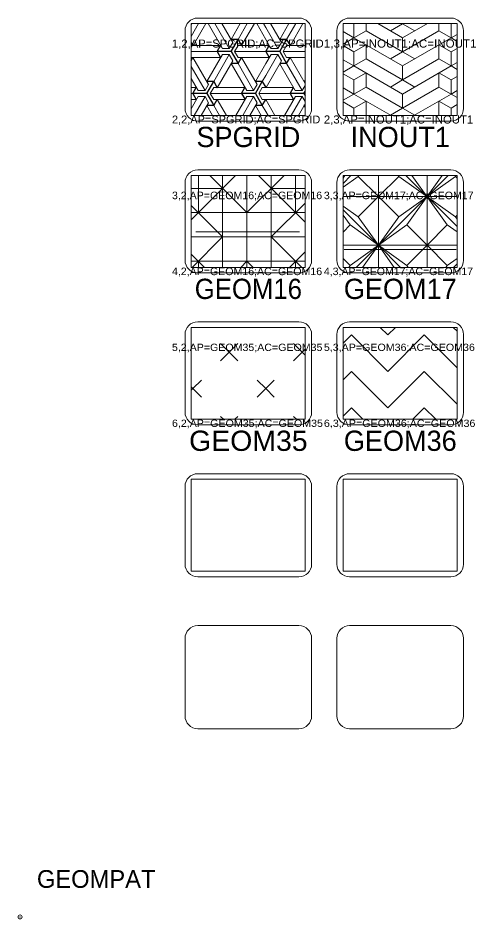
# Model space of a CAD drawing. Extents: x 95935 to 95946.4, y 95971.2 to 95974.7.
# Drawn here: x 95935.026 to 95936.835, y 95971.173 to 95974.732 of the extents above; entities that cross this region are included whole.
import ezdxf
from ezdxf.enums import TextEntityAlignment as Align

# ---------------------------------------------------------------- set-up
doc = ezdxf.new("R2010")
doc.units = 0
doc.header["$LTSCALE"] = 0.032
doc.header["$PDMODE"] = 32
doc.header["$PDSIZE"] = 0.016
for name, color, linetype, lineweight in [('1', 7, 'Continuous', 13), ('2', 7, 'Continuous', 13), ('25', 7, 'Continuous', 13), ('6', 7, 'Continuous', 13), ('63', 7, 'Continuous', 13)]:
    doc.layers.add(name, color=color, linetype=linetype, lineweight=lineweight)
doc.layers.add('20', color=7, linetype='Continuous')
doc.layers.add('8', color=7, linetype='Continuous')

msp = doc.modelspace()

# ---------------------------------------------------------------- linework, layer by layer
at = {"layer": '1'}
for p, q in [((95935.7357, 95974.7318), (95936.1357, 95974.7318)), ((95936.3357, 95974.7318), (95936.7357, 95974.7318)), ((95935.6857, 95974.3747), (95935.6857, 95974.6818)), ((95936.1857, 95974.6818), (95936.1857, 95974.3747)), ((95936.2857, 95974.3747), (95936.2857, 95974.6818)), ((95936.7857, 95974.6818), (95936.7857, 95974.3747)), ((95936.1357, 95974.3247), (95935.7357, 95974.3247)), ((95936.7357, 95974.3247), (95936.3357, 95974.3247)), ((95935.7357, 95974.1318), (95936.1357, 95974.1318)), ((95936.3357, 95974.1318), (95936.7357, 95974.1318)), ((95935.6857, 95973.7747), (95935.6857, 95974.0818)), ((95936.1857, 95974.0818), (95936.1857, 95973.7747)), ((95936.2857, 95973.7747), (95936.2857, 95974.0818)), ((95936.7857, 95974.0818), (95936.7857, 95973.7747)), ((95936.1357, 95973.7247), (95935.7357, 95973.7247)), ((95936.7357, 95973.7247), (95936.3357, 95973.7247)), ((95935.7357, 95973.5318), (95936.1357, 95973.5318)), ((95936.3357, 95973.5318), (95936.7357, 95973.5318)), ((95935.6857, 95973.1747), (95935.6857, 95973.4818)), ((95936.1857, 95973.4818), (95936.1857, 95973.1747)), ((95936.2857, 95973.1747), (95936.2857, 95973.4818)), ((95936.7857, 95973.4818), (95936.7857, 95973.1747)), ((95936.1357, 95973.1247), (95935.7357, 95973.1247)), ((95936.7357, 95973.1247), (95936.3357, 95973.1247)), ((95935.7357, 95972.9318), (95936.1357, 95972.9318)), ((95936.3357, 95972.9318), (95936.7357, 95972.9318)), ((95935.6857, 95972.5747), (95935.6857, 95972.8818)), ((95936.1857, 95972.8818), (95936.1857, 95972.5747)), ((95936.2857, 95972.5747), (95936.2857, 95972.8818)), ((95936.7857, 95972.8818), (95936.7857, 95972.5747)), ((95936.1357, 95972.5247), (95935.7357, 95972.5247)), ((95936.7357, 95972.5247), (95936.3357, 95972.5247)), ((95935.7357, 95972.3318), (95936.1357, 95972.3318)), ((95936.3357, 95972.3318), (95936.7357, 95972.3318)), ((95935.6857, 95971.9747), (95935.6857, 95972.2818)), ((95936.1857, 95972.2818), (95936.1857, 95971.9747)), ((95936.2857, 95971.9747), (95936.2857, 95972.2818)), ((95936.7857, 95972.2818), (95936.7857, 95971.9747)), ((95936.1357, 95971.9247), (95935.7357, 95971.9247)), ((95936.7357, 95971.9247), (95936.3357, 95971.9247))]:
    msp.add_line(p, q, dxfattribs=at)
for centre, start, end in [((95935.7357, 95974.6818), 90, 180), ((95936.1357, 95974.6818), 0, 90), ((95936.3357, 95974.6818), 90, 180), ((95936.7357, 95974.6818), 0, 90), ((95935.7357, 95974.3747), 180, 270), ((95936.1357, 95974.3747), 270, 0), ((95936.3357, 95974.3747), 180, 270), ((95936.7357, 95974.3747), 270, 0), ((95935.7357, 95974.0818), 90, 180), ((95936.1357, 95974.0818), 0, 90), ((95936.3357, 95974.0818), 90, 180), ((95936.7357, 95974.0818), 0, 90), ((95935.7357, 95973.7747), 180, 270), ((95936.1357, 95973.7747), 270, 0), ((95936.3357, 95973.7747), 180, 270), ((95936.7357, 95973.7747), 270, 0), ((95935.7357, 95973.4818), 90, 180), ((95936.1357, 95973.4818), 0, 90), ((95936.3357, 95973.4818), 90, 180), ((95936.7357, 95973.4818), 0, 90), ((95935.7357, 95973.1747), 180, 270), ((95936.1357, 95973.1747), 270, 0), ((95936.3357, 95973.1747), 180, 270), ((95936.7357, 95973.1747), 270, 0), ((95935.7357, 95972.8818), 90, 180), ((95936.1357, 95972.8818), 0, 90), ((95936.3357, 95972.8818), 90, 180), ((95936.7357, 95972.8818), 0, 90), ((95935.7357, 95972.5747), 180, 270), ((95936.1357, 95972.5747), 270, 0), ((95936.3357, 95972.5747), 180, 270), ((95936.7357, 95972.5747), 270, 0), ((95935.7357, 95972.2818), 90, 180), ((95936.1357, 95972.2818), 0, 90), ((95936.3357, 95972.2818), 90, 180), ((95936.7357, 95972.2818), 0, 90), ((95935.7357, 95971.9747), 180, 270), ((95936.1357, 95971.9747), 270, 0), ((95936.3357, 95971.9747), 180, 270), ((95936.7357, 95971.9747), 270, 0)]:
    msp.add_arc(centre, 0.05, start, end, dxfattribs=at)
at = {"layer": '2'}
for points in [[(95936.1601, 95974.7099), (95935.7097, 95974.7099), (95935.7097, 95974.3468), (95936.1601, 95974.3468)], [(95936.7601, 95974.7099), (95936.3097, 95974.7099), (95936.3097, 95974.3468), (95936.7601, 95974.3468)], [(95936.1601, 95974.1099), (95935.7097, 95974.1099), (95935.7097, 95973.7468), (95936.1601, 95973.7468)], [(95936.7601, 95974.1099), (95936.3097, 95974.1099), (95936.3097, 95973.7468), (95936.7601, 95973.7468)], [(95936.1601, 95973.5099), (95935.7097, 95973.5099), (95935.7097, 95973.1468), (95936.1601, 95973.1468)], [(95936.7601, 95973.5099), (95936.3097, 95973.5099), (95936.3097, 95973.1468), (95936.7601, 95973.1468)], [(95936.1601, 95972.9099), (95935.7097, 95972.9099), (95935.7097, 95972.5468), (95936.1601, 95972.5468)], [(95936.7601, 95972.9099), (95936.3097, 95972.9099), (95936.3097, 95972.5468), (95936.7601, 95972.5468)]]:
    msp.add_lwpolyline(points, close=True, dxfattribs=at)
at = {"layer": '25'}
msp.add_line((95935.7278, 95973.8875), (95936.1378, 95973.8875), dxfattribs=at)
at = {"layer": '6'}
for p, q in [((95935.7097, 95974.7059), (95935.712, 95974.7099)), ((95935.7097, 95974.6592), (95935.739, 95974.7099)), ((95935.7177, 95974.6236), (95935.7675, 95974.7099)), ((95935.7765, 95974.7099), (95935.8332, 95974.6118)), ((95935.8039, 95974.7099), (95935.8606, 95974.6118)), ((95935.8314, 95974.7099), (95935.8743, 95974.6355)), ((95935.8679, 95974.6474), (95935.904, 95974.7099)), ((95935.8949, 95974.6474), (95935.931, 95974.7099)), ((95935.9092, 95974.6227), (95935.9595, 95974.7099)), ((95935.9686, 95974.7099), (95936.0046, 95974.6474)), ((95935.996, 95974.7099), (95936.0046, 95974.6949)), ((95936.0046, 95974.6949), (95936.0526, 95974.6118)), ((95936.0234, 95974.7099), (95936.0663, 95974.6355)), ((95936.0597, 95974.647), (95936.096, 95974.7099)), ((95936.0869, 95974.6474), (95936.123, 95974.7099)), ((95936.1017, 95974.6236), (95936.1515, 95974.7099)), ((95936.3526, 95974.7087), (95936.3505, 95974.7099)), ((95936.3526, 95974.7087), (95936.3547, 95974.7099)), ((95936.3526, 95974.6533), (95936.3526, 95974.7087)), ((95936.4006, 95974.681), (95936.4006, 95974.7099)), ((95936.5446, 95974.6533), (95936.4465, 95974.7099)), ((95936.5446, 95974.7087), (95936.4966, 95974.681)), ((95936.5425, 95974.7099), (95936.5446, 95974.7087)), ((95936.5446, 95974.6533), (95936.6427, 95974.7099)), ((95936.5446, 95974.7099), (95936.5446, 95974.7087)), ((95936.5467, 95974.7099), (95936.5446, 95974.7087)), ((95936.5446, 95974.7087), (95936.5926, 95974.681)), ((95936.6886, 95974.681), (95936.6886, 95974.7099)), ((95936.7366, 95974.7087), (95936.7345, 95974.7099)), ((95936.7366, 95974.7087), (95936.7387, 95974.7099)), ((95936.7366, 95974.6533), (95936.7366, 95974.7087)), ((95936.3526, 95974.6533), (95936.3097, 95974.6781)), ((95936.3526, 95974.6533), (95936.3097, 95974.6285)), ((95936.3526, 95974.6533), (95936.4006, 95974.681)), ((95936.3526, 95974.6533), (95936.4486, 95974.5979)), ((95936.4006, 95974.681), (95936.5446, 95974.5979)), ((95936.6886, 95974.681), (95936.5446, 95974.5979)), ((95936.5446, 95974.6533), (95936.5446, 95974.5979)), ((95936.7366, 95974.6533), (95936.6406, 95974.5979)), ((95936.7366, 95974.6533), (95936.6886, 95974.681)), ((95936.7366, 95974.6533), (95936.7601, 95974.6669)), ((95936.7366, 95974.6533), (95936.7601, 95974.6397)), ((95935.7097, 95974.6236), (95935.8263, 95974.6236)), ((95935.8606, 95974.6118), (95935.8743, 95974.6355)), ((95935.8812, 95974.5999), (95935.8949, 95974.6236)), ((95935.8949, 95974.6236), (95936.0046, 95974.6236)), ((95936.0046, 95974.6474), (95936.0252, 95974.6118)), ((95936.0046, 95974.6236), (95936.0183, 95974.6236)), ((95936.0526, 95974.6118), (95936.0663, 95974.6355)), ((95936.0732, 95974.5999), (95936.0869, 95974.6236)), ((95936.0869, 95974.6236), (95936.1601, 95974.6236)), ((95936.3526, 95974.5979), (95936.3097, 95974.6227)), ((95936.3526, 95974.5979), (95936.4006, 95974.6256)), ((95936.4006, 95974.5979), (95936.4006, 95974.6256)), ((95936.7366, 95974.5979), (95936.6886, 95974.6256)), ((95936.6886, 95974.5979), (95936.6886, 95974.6256)), ((95935.7097, 95974.5999), (95935.8126, 95974.5999)), ((95935.7719, 95974.4811), (95935.8337, 95974.588)), ((95935.7989, 95974.4811), (95935.8606, 95974.588)), ((95935.8606, 95974.6118), (95935.8332, 95974.6118)), ((95935.8606, 95974.588), (95935.8337, 95974.588)), ((95935.8606, 95974.588), (95935.8749, 95974.5633)), ((95935.8812, 95974.5999), (95936.0046, 95974.5999)), ((95935.8812, 95974.5999), (95935.8949, 95974.5761)), ((95936.0046, 95974.5049), (95936.0526, 95974.588)), ((95936.0046, 95974.5515), (95936.0257, 95974.588)), ((95936.0526, 95974.6118), (95936.0252, 95974.6118)), ((95936.0526, 95974.588), (95936.0257, 95974.588)), ((95936.0526, 95974.588), (95936.0669, 95974.5633)), ((95936.0732, 95974.5999), (95936.0869, 95974.5761)), ((95936.0732, 95974.5999), (95936.1601, 95974.5999)), ((95936.3526, 95974.5424), (95936.3526, 95974.5979)), ((95936.4006, 95974.5701), (95936.4006, 95974.5979)), ((95936.5446, 95974.5424), (95936.4486, 95974.5979)), ((95936.5446, 95974.5979), (95936.4966, 95974.5701)), ((95936.5446, 95974.5424), (95936.6406, 95974.5979)), ((95936.5446, 95974.5979), (95936.5926, 95974.5701)), ((95936.6886, 95974.5701), (95936.6886, 95974.5979)), ((95936.7366, 95974.5979), (95936.7601, 95974.6115)), ((95936.7366, 95974.5424), (95936.7366, 95974.5979)), ((95935.7097, 95974.5761), (95935.8263, 95974.5761)), ((95935.7166, 95974.5761), (95935.7783, 95974.4692)), ((95935.8132, 95974.4564), (95935.8749, 95974.5633)), ((95935.8675, 95974.5524), (95935.9292, 95974.4455)), ((95935.8949, 95974.5761), (95936.0046, 95974.5761)), ((95935.8949, 95974.5524), (95935.9566, 95974.4455)), ((95935.9086, 95974.5761), (95935.9703, 95974.4692)), ((95935.9639, 95974.4811), (95936.0046, 95974.5515)), ((95936.0046, 95974.5761), (95936.0183, 95974.5761)), ((95936.0057, 95974.4574), (95936.0669, 95974.5633)), ((95936.06, 95974.5514), (95936.1212, 95974.4455)), ((95936.0869, 95974.5761), (95936.1601, 95974.5761)), ((95936.0869, 95974.5524), (95936.1486, 95974.4455)), ((95936.1006, 95974.5761), (95936.1601, 95974.473)), ((95936.3526, 95974.5424), (95936.4006, 95974.5701)), ((95936.4006, 95974.5701), (95936.5446, 95974.487)), ((95936.6886, 95974.5701), (95936.5446, 95974.487)), ((95936.7366, 95974.5424), (95936.6886, 95974.5701)), ((95935.7097, 95974.5406), (95935.7646, 95974.4455)), ((95936.3526, 95974.487), (95936.3097, 95974.5118)), ((95936.5446, 95974.4316), (95936.3526, 95974.5424)), ((95936.4006, 95974.4593), (95936.4006, 95974.5147)), ((95936.5446, 95974.4316), (95936.7366, 95974.5424)), ((95936.5446, 95974.5424), (95936.5446, 95974.487)), ((95936.6886, 95974.4593), (95936.6886, 95974.5147)), ((95935.7097, 95974.4931), (95935.7372, 95974.4455)), ((95935.9909, 95974.4811), (95936.0046, 95974.5049)), ((95936.1559, 95974.4811), (95936.1601, 95974.4884)), ((95936.5446, 95974.487), (95936.4966, 95974.4593)), ((95936.5446, 95974.487), (95936.5926, 95974.4593)), ((95936.7366, 95974.487), (95936.7601, 95974.5006)), ((95935.7097, 95974.4574), (95935.7303, 95974.4574)), ((95935.7646, 95974.4455), (95935.7372, 95974.4455)), ((95935.7646, 95974.4455), (95935.7783, 95974.4692)), ((95935.7852, 95974.4336), (95935.7989, 95974.4574)), ((95935.7989, 95974.4574), (95935.9223, 95974.4574)), ((95935.9566, 95974.4455), (95935.9292, 95974.4455)), ((95935.9566, 95974.4455), (95935.9703, 95974.4692)), ((95935.9772, 95974.4336), (95935.9909, 95974.4574)), ((95935.9909, 95974.4574), (95936.0046, 95974.4574)), ((95936.0057, 95974.4574), (95936.1143, 95974.4574)), ((95936.1486, 95974.4455), (95936.1212, 95974.4455)), ((95936.1486, 95974.4455), (95936.1601, 95974.4654)), ((95936.3526, 95974.4316), (95936.3097, 95974.4564)), ((95936.3526, 95974.4316), (95936.4006, 95974.4593)), ((95936.4006, 95974.4593), (95936.5446, 95974.3761)), ((95936.6886, 95974.4593), (95936.5446, 95974.3762)), ((95936.7366, 95974.4316), (95936.6886, 95974.4593)), ((95936.7366, 95974.4316), (95936.7601, 95974.4452)), ((95935.7097, 95974.4336), (95935.7166, 95974.4336)), ((95935.7097, 95974.3732), (95935.7377, 95974.4217)), ((95935.7097, 95974.4098), (95935.7303, 95974.4098)), ((95935.7214, 95974.3468), (95935.7646, 95974.4217)), ((95935.7646, 95974.4217), (95935.7377, 95974.4217)), ((95935.7646, 95974.4217), (95935.7789, 95974.397)), ((95935.7852, 95974.4336), (95935.7989, 95974.4098)), ((95935.7852, 95974.4336), (95935.9086, 95974.4336)), ((95935.7989, 95974.4098), (95935.9228, 95974.4098)), ((95935.8126, 95974.4098), (95935.849, 95974.3468)), ((95935.8864, 95974.3468), (95935.9297, 95974.4217)), ((95935.9134, 95974.3468), (95935.9566, 95974.4217)), ((95935.9566, 95974.4217), (95935.9297, 95974.4217)), ((95935.9566, 95974.4217), (95935.9709, 95974.397)), ((95935.9772, 95974.4336), (95935.9909, 95974.4098)), ((95935.9772, 95974.4336), (95936.0046, 95974.4336)), ((95935.9909, 95974.4098), (95936.0046, 95974.4098)), ((95936.0046, 95974.4336), (95936.1006, 95974.4336)), ((95936.0046, 95974.4098), (95936.1143, 95974.4098)), ((95936.0046, 95974.4098), (95936.041, 95974.3468)), ((95936.0784, 95974.3468), (95936.1217, 95974.4217)), ((95936.1054, 95974.3468), (95936.1486, 95974.4217)), ((95936.1486, 95974.4217), (95936.1217, 95974.4217)), ((95936.1486, 95974.4217), (95936.1601, 95974.4018)), ((95936.3097, 95974.4068), (95936.3526, 95974.4316)), ((95936.4994, 95974.3468), (95936.3526, 95974.4316)), ((95936.3526, 95974.3761), (95936.4006, 95974.4039)), ((95936.4006, 95974.3484), (95936.4006, 95974.4039)), ((95936.5446, 95974.4316), (95936.5446, 95974.3762)), ((95936.5898, 95974.3468), (95936.7366, 95974.4316)), ((95936.7366, 95974.3762), (95936.6886, 95974.4039)), ((95936.6886, 95974.3484), (95936.6886, 95974.4039)), ((95936.7601, 95974.418), (95936.7366, 95974.4316)), ((95935.7499, 95974.3468), (95935.7789, 95974.397)), ((95935.7715, 95974.3861), (95935.7942, 95974.3468)), ((95935.7989, 95974.3861), (95935.8216, 95974.3468)), ((95935.9419, 95974.3468), (95935.9709, 95974.397)), ((95935.9635, 95974.3861), (95935.9862, 95974.3468)), ((95935.9909, 95974.3861), (95936.0046, 95974.3623)), ((95936.1339, 95974.3468), (95936.1601, 95974.3922)), ((95936.1555, 95974.3861), (95936.1601, 95974.3781)), ((95936.5446, 95974.3761), (95936.4966, 95974.3484)), ((95936.5446, 95974.3762), (95936.5926, 95974.3484)), ((95936.0046, 95974.3623), (95936.0136, 95974.3468)), ((95936.3978, 95974.3468), (95936.4006, 95974.3484)), ((95936.4006, 95974.3484), (95936.4034, 95974.3468)), ((95936.6886, 95974.3484), (95936.6858, 95974.3468)), ((95936.6914, 95974.3468), (95936.6886, 95974.3484)), ((95935.8852, 95974.1099), (95935.7097, 95973.9344)), ((95935.7383, 95974.1099), (95935.7383, 95973.963)), ((95935.7834, 95974.1099), (95935.9303, 95973.963)), ((95935.8343, 95974.1099), (95935.8343, 95973.7468)), ((95935.9303, 95974.1099), (95935.9303, 95973.7468)), ((95935.9303, 95973.963), (95936.0772, 95974.1099)), ((95936.1601, 95973.9252), (95935.9754, 95974.1099)), ((95936.0263, 95974.1099), (95936.0263, 95973.7468)), ((95936.1223, 95974.1099), (95936.1223, 95973.963)), ((95936.3411, 95974.1099), (95936.3097, 95974.0785)), ((95936.3097, 95974.0994), (95936.3172, 95974.1099)), ((95936.4495, 95974.1099), (95936.4495, 95973.7468)), ((95936.7251, 95974.1099), (95936.4495, 95973.8343)), ((95936.4495, 95974.0263), (95936.5295, 95974.1063)), ((95936.5295, 95974.1063), (95936.5269, 95974.1099)), ((95936.7535, 95973.9463), (95936.5295, 95974.1063)), ((95936.5579, 95974.1099), (95936.7601, 95973.9077)), ((95936.5615, 95973.9143), (95936.7012, 95974.1099)), ((95936.6415, 95974.1099), (95936.6415, 95973.7468)), ((95935.7097, 95974.059), (95935.8343, 95974.059)), ((95936.0263, 95974.059), (95936.1601, 95974.059)), ((95936.3097, 95974.0263), (95936.7601, 95974.0263)), ((95936.5295, 95973.9463), (95936.4495, 95974.0263)), ((95935.8343, 95973.867), (95935.7097, 95973.9916)), ((95936.1601, 95974.0008), (95936.0263, 95973.867)), ((95936.3695, 95973.9463), (95936.3097, 95973.989)), ((95935.7097, 95973.963), (95936.1601, 95973.963)), ((95936.3097, 95973.9741), (95936.4495, 95973.8343)), ((95936.3097, 95973.9532), (95936.3375, 95973.9143)), ((95936.7601, 95973.9529), (95936.7535, 95973.9463)), ((95936.7601, 95973.9371), (95936.7535, 95973.9463)), ((95936.3375, 95973.9143), (95936.3097, 95973.8865)), ((95936.4495, 95973.8343), (95936.5615, 95973.9143)), ((95935.7097, 95973.867), (95936.1601, 95973.867)), ((95935.7141, 95973.7468), (95935.8343, 95973.867)), ((95936.0263, 95973.867), (95936.1465, 95973.7468)), ((95936.3097, 95973.8343), (95936.7601, 95973.8343)), ((95936.3375, 95973.7543), (95936.4495, 95973.8343)), ((95936.4495, 95973.8343), (95936.362, 95973.7468)), ((95936.4495, 95973.8343), (95936.387, 95973.7468)), ((95936.4495, 95973.8343), (95936.537, 95973.7468)), ((95936.512, 95973.7468), (95936.4495, 95973.8343)), ((95935.7097, 95973.7996), (95935.7625, 95973.7468)), ((95936.0981, 95973.7468), (95936.1601, 95973.8088)), ((95935.7097, 95973.771), (95936.1601, 95973.771)), ((95935.7383, 95973.771), (95935.7383, 95973.7468)), ((95935.9303, 95973.771), (95935.9061, 95973.7468)), ((95935.9545, 95973.7468), (95935.9303, 95973.771)), ((95936.1223, 95973.771), (95936.1223, 95973.7468)), ((95936.3097, 95973.7821), (95936.3375, 95973.7543)), ((95936.3321, 95973.7468), (95936.3375, 95973.7543)), ((95936.5615, 95973.7543), (95936.5669, 95973.7468)), ((95936.7601, 95973.7609), (95936.746, 95973.7468)), ((95936.3097, 95973.4473), (95936.3426, 95973.4802)), ((95936.3426, 95973.4802), (95936.4866, 95973.3362)), ((95936.4569, 95973.5099), (95936.4866, 95973.4802)), ((95936.4866, 95973.4802), (95936.5163, 95973.5099)), ((95936.4866, 95973.3362), (95936.6306, 95973.4802)), ((95936.6306, 95973.4802), (95936.7601, 95973.3507)), ((95936.7449, 95973.5099), (95936.7601, 95973.4947)), ((95935.8263, 95973.3781), (95935.8941, 95973.4459)), ((95935.8263, 95973.4459), (95935.8941, 95973.3781)), ((95936.1143, 95973.4459), (95936.1601, 95973.4001)), ((95936.1143, 95973.3781), (95936.1601, 95973.4239)), ((95936.3097, 95973.3033), (95936.3426, 95973.3362)), ((95936.3426, 95973.3362), (95936.4866, 95973.1922)), ((95936.4866, 95973.1922), (95936.6306, 95973.3362)), ((95936.6306, 95973.3362), (95936.7601, 95973.2067)), ((95935.7162, 95973.268), (95935.7501, 95973.3019)), ((95936.0042, 95973.268), (95936.0381, 95973.3019)), ((95935.7097, 95973.2745), (95935.7162, 95973.268)), ((95935.7097, 95973.2615), (95935.7162, 95973.268)), ((95935.7162, 95973.268), (95935.7501, 95973.2341)), ((95935.9703, 95973.2341), (95936.0042, 95973.268)), ((95935.8263, 95973.1579), (95935.8374, 95973.1468)), ((95935.883, 95973.1468), (95935.8941, 95973.1579)), ((95936.1143, 95973.1579), (95936.1254, 95973.1468))]:
    msp.add_line(p, q, dxfattribs=at)
at = {"layer": '6', "lineweight": 25}
for p, q in [((95935.7097, 95974.6356), (95935.7166, 95974.6236)), ((95935.8126, 95974.5999), (95935.8263, 95974.6236)), ((95935.8675, 95974.5999), (95935.8949, 95974.6474)), ((95935.8949, 95974.6474), (95935.8679, 95974.6474)), ((95935.8949, 95974.6474), (95935.9092, 95974.6227)), ((95936.0046, 95974.5999), (95936.0183, 95974.6236)), ((95936.0595, 95974.5999), (95936.0869, 95974.6474)), ((95936.0869, 95974.6474), (95936.0595, 95974.6474)), ((95936.0869, 95974.6474), (95936.1006, 95974.6236)), ((95935.8675, 95974.5999), (95935.8126, 95974.5999)), ((95935.8126, 95974.5999), (95935.8263, 95974.5761)), ((95935.8675, 95974.5999), (95935.8949, 95974.5524)), ((95936.0595, 95974.5999), (95936.0046, 95974.5999)), ((95936.0046, 95974.5999), (95936.0183, 95974.5761)), ((95936.0595, 95974.5999), (95936.0869, 95974.5524)), ((95935.7097, 95974.5642), (95935.7166, 95974.5761)), ((95935.8949, 95974.5524), (95935.8675, 95974.5524)), ((95935.8949, 95974.5524), (95935.9086, 95974.5761)), ((95936.0869, 95974.5524), (95936.0606, 95974.5524)), ((95936.0869, 95974.5524), (95936.1006, 95974.5761)), ((95935.7715, 95974.4336), (95935.7989, 95974.4811)), ((95935.7989, 95974.4811), (95935.7719, 95974.4811)), ((95935.7989, 95974.4811), (95935.8132, 95974.4564)), ((95935.9635, 95974.4336), (95935.9909, 95974.4811)), ((95935.9909, 95974.4811), (95935.9639, 95974.4811)), ((95935.9909, 95974.4811), (95936.0046, 95974.4574)), ((95936.1601, 95974.4811), (95936.1559, 95974.4811)), ((95935.7166, 95974.4336), (95935.7303, 95974.4574)), ((95935.9086, 95974.4336), (95935.9223, 95974.4574)), ((95936.1006, 95974.4336), (95936.1143, 95974.4574)), ((95936.1555, 95974.4336), (95936.1601, 95974.4416)), ((95935.7166, 95974.4336), (95935.7303, 95974.4098)), ((95935.7715, 95974.4336), (95935.7166, 95974.4336)), ((95935.7715, 95974.4336), (95935.7989, 95974.3861)), ((95935.7989, 95974.3861), (95935.8126, 95974.4098)), ((95935.9086, 95974.4336), (95935.9226, 95974.4094)), ((95935.9635, 95974.4336), (95935.9086, 95974.4336)), ((95935.9635, 95974.4336), (95935.9909, 95974.3861)), ((95935.9909, 95974.3861), (95936.0046, 95974.4098)), ((95936.1006, 95974.4336), (95936.1143, 95974.4098)), ((95936.1555, 95974.4336), (95936.1006, 95974.4336)), ((95936.1555, 95974.4336), (95936.1601, 95974.4256)), ((95935.7989, 95974.3861), (95935.7715, 95974.3861)), ((95935.9909, 95974.3861), (95935.9635, 95974.3861)), ((95936.1601, 95974.3861), (95936.1555, 95974.3861))]:
    msp.add_line(p, q, dxfattribs=at)
at = {"layer": '6'}
for points in [[(95936.3097, 95974.5176), (95936.3526, 95974.5424), (95936.3097, 95974.5672)], [(95936.7601, 95974.5288), (95936.7366, 95974.5424), (95936.7601, 95974.556)], [(95936.3526, 95974.4316), (95936.3526, 95974.487), (95936.4006, 95974.5147)], [(95936.7366, 95974.4316), (95936.7366, 95974.487), (95936.6886, 95974.5147)], [(95936.3526, 95974.3468), (95936.3526, 95974.3761), (95936.3097, 95974.4009)], [(95936.7366, 95974.3468), (95936.7366, 95974.3762), (95936.7601, 95974.3898)], [(95936.3721, 95974.1099), (95936.3695, 95974.1063), (95936.3097, 95974.0636)], [(95936.3695, 95974.1063), (95936.4495, 95974.0263), (95936.3695, 95973.9463)], [(95936.7535, 95974.1063), (95936.5295, 95973.9463), (95936.4495, 95973.8343)], [(95936.5818, 95974.1099), (95936.7215, 95973.9143), (95936.7601, 95973.8867)], [(95936.7561, 95974.1099), (95936.7535, 95974.1063), (95936.7601, 95974.0997)], [(95936.3375, 95973.9143), (95936.4495, 95973.8343), (95936.3695, 95973.9463)], [(95936.7215, 95973.9143), (95936.6415, 95973.8343), (95936.5615, 95973.9143)], [(95936.4495, 95973.8343), (95936.5615, 95973.7543), (95936.6415, 95973.8343), (95936.7215, 95973.7543)], [(95936.7161, 95973.7468), (95936.7215, 95973.7543), (95936.7601, 95973.7819)], [(95935.9703, 95973.3019), (95936.0042, 95973.268), (95936.0381, 95973.2341)], [(95936.3097, 95973.1593), (95936.3426, 95973.1922), (95936.388, 95973.1468)], [(95936.5852, 95973.1468), (95936.6306, 95973.1922), (95936.676, 95973.1468)]]:
    msp.add_lwpolyline(points, dxfattribs=at)
at = {"layer": '63'}
msp.add_line((95936.7569, 95973.8178), (95936.3141, 95973.8178), dxfattribs=at)
msp.add_point((95935.0341, 95971.1811), dxfattribs=at)

# ---------------------------------------------------------------- texts
at = {"layer": '20'}
for s, p in [('SPGRID', (95935.9358, 95974.222)), ('INOUT1', (95936.5357, 95974.222)), ('GEOM17', (95936.5357, 95973.622)), ('GEOM36', (95936.5358, 95973.022))]:
    msp.add_text(s, height=0.08, dxfattribs=at).set_placement(p, align=Align.CENTER)
for s, width, p in [('GEOM16', 0.95, (95935.9358, 95973.622)), ('GEOM35', 1.05, (95935.9358, 95973.022))]:
    msp.add_text(s, height=0.08, dxfattribs=dict(at, width=width)).set_placement(p, align=Align.CENTER)
at = {"layer": '63'}
for s, height, width, p in [('1,2,AP=SPGRID;AC=SPGRID', 0.0316, 1.05, (95935.6341, 95974.6153)), ('1,3,AP=INOUT1;AC=INOUT1', 0.0326, 1.05, (95936.2341, 95974.6148)), ('2,2,AP=SPGRID;AC=SPGRID', 0.0309, 1.05, (95935.6341, 95974.3156)), ('2,3,AP=INOUT1;AC=INOUT1', 0.0319, 1.05, (95936.2341, 95974.3151)), ('3,2,AP=GEOM16;AC=GEOM16', 0.0298, 1.05, (95935.6341, 95974.0162)), ('3,3,AP=GEOM17;AC=GEOM17', 0.0297, 1.05, (95936.2341, 95974.0162)), ('4,2,AP=GEOM16;AC=GEOM16', 0.0298, 1.05, (95935.6341, 95973.7162)), ('4,3,AP=GEOM17;AC=GEOM17', 0.0296, 1.05, (95936.2341, 95973.7163)), ('5,2,AP=GEOM35;AC=GEOM35', 0.0285, 1.1, (95935.6341, 95973.4168)), ('5,3,AP=GEOM36;AC=GEOM36', 0.0286, 1.1, (95936.2341, 95973.4168)), ('6,2,AP=GEOM35;AC=GEOM35', 0.0286, 1.1, (95935.6341, 95973.1168)), ('6,3,AP=GEOM36;AC=GEOM36', 0.0287, 1.1, (95936.2341, 95973.1167))]:
    msp.add_text(s, height=height, dxfattribs=dict(at, width=width)).set_placement(p)
at = {"layer": '8'}
msp.add_text('GEOMPAT', height=0.07, dxfattribs=at).set_placement((95935.3348, 95971.2961), align=Align.CENTER)

doc.saveas('drawing.dxf')
